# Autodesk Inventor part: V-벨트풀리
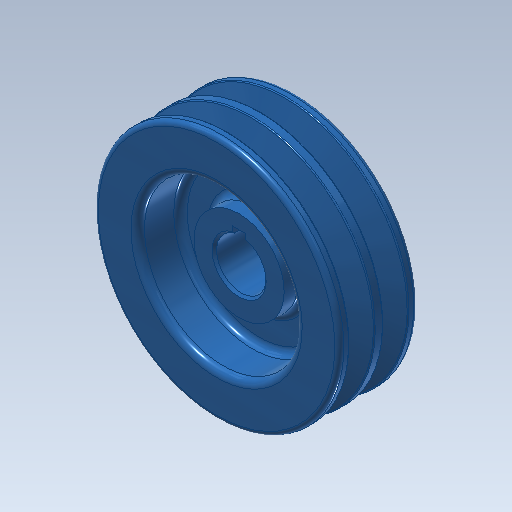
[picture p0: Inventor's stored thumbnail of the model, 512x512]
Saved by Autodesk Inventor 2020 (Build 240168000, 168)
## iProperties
CustomPartVersion: 1
Created: 2021-06
Part Number: V-벨트풀리
Material: 알루미늄 6061
Document SubType Name: Modeling
Designer: mdu
Density: 1 g/cm^3
Appearance: 청록색
Author: mdu
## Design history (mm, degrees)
sketch "주 스케치"
  geometry: L1 (0, 35)-(54.5, 35); L2 (54.5, 35)-(54.5, 15.55); L3 (54.5, 15.55)-(42, 11.488); L4 (42, 11.488)-(42, 8.512); L5 (42, 8.512)-(54.5, 4.45); L6 (54.5, 4.45)-(54.5, 0); L7 (54.5, 0)-(0, 0); L8 (50.5, 14.25)-(50.5, 5.75); L9 (42, 10)-(50.5, 10); L10 (54.5, 15.55)-(54.5, 4.45); L11 (0, -4)-(0, 24) reference; L12 (0, 0)-(0, 35)
  constraints: 22 end point, 5 perpendicular, 2 collinear, 2 midpoint, 2 point on line, 1 parallel
  dimensions: "d0" = 8.5 distance of L8.start L8.end (= da_Bw); "d1" = 36 deg angle of L3 L5 (= da_Alfa); "d2" = 4 distance between parallel lines of L2 L8 (= da_c); "d6" = 35 distance between parallel lines of L7 L1 (computed from d5, da_ng, da_Sg); "d21" = 101 diameter of L8 L11 (= da_Dw); "d25" = 12.5 distance between parallel lines of L4 L10 (= da_Hd); "d27" = 10 distance between parallel lines of L7 L9 (= da_Se)
node "평 벨트"
revolve "본체" stored, may be unused: angle "d7" = 90 deg
revolve "그루브" stored, may be unused: angle "d15" = 90 deg
fillet "외부 모깎기" dims "d8" = 0.5 (= da_r1), "d10" = 0, "da_r1" = 0.5 [user parameter; used in 1 equation term]
fillet "내부 모깎기" dims "d9" = 1 (= da_r2), "d11" = 0, "da_r2" = 1 [user parameter; used in 1 equation term]
sketch "스케치2"
  geometry: L1 (0, 0)-(0, 35); L2 (-54.5, 35)-(54.5, 35) reference; L3 (0, 35)-(35, 35); L4 (35, 35)-(35, 16); L5 (35, 16)-(20, 16); L6 (20, 16)-(20, 25); L7 (20, 25)-(0, 25); L8 (35, 0)-(35, 6); L9 (35, 6)-(20, 6); L10 (20, 6)-(20, 0); L11 (20, 0)-(35, 0); L12 (-54.5, 0)-(54.5, 0) reference
  constraints: 20 end point, 5 perpendicular, 3 parallel, 2 point on line, 2 vertical alignment, 1 collinear, 1 midpoint, 1 vertical
  dimensions: "d28" = 9 distance between parallel lines of L7 L5; "d30" = 6 distance of L9.end L10.end; "d31" = 10 distance between parallel lines of L9 L5; "d32" = 40 diameter of L10 L1; "d33" = 70 diameter of L8 L1
revolve "회전3" sketch "스케치2" stored, may be unused: angle "d34" = 90 deg
fillet "모깎기3" dims "d35" = 2, "d36" = 3
node "키홈1"
chamfer "모따기1" distance "d37" = 1; stored, may be unused: second distance "d38" = 2, angle "d39" = 45 deg
body "Solid1"
pattern_linear "그루브 패턴" dims "d18" = 15 (= da_Sg)
feature "허브 키홈"
other parameters: "da_Bw" = 8.5 [user parameter; used in 1 equation term], "da_Alfa" = 36 deg [user parameter; used in 1 equation term], "da_c" = 4 [user parameter; used in 1 equation term], "da_Dw" = 101 [user parameter; used in 1 equation term], "da_Hd" = 12.5 [user parameter; used in 1 equation term], "da_Se" = 10 [user parameter; used in 2 equation terms], "da_Sg" = 15 [user parameter; used in 2 equation terms], "d24" = 0, "d26" = 0
